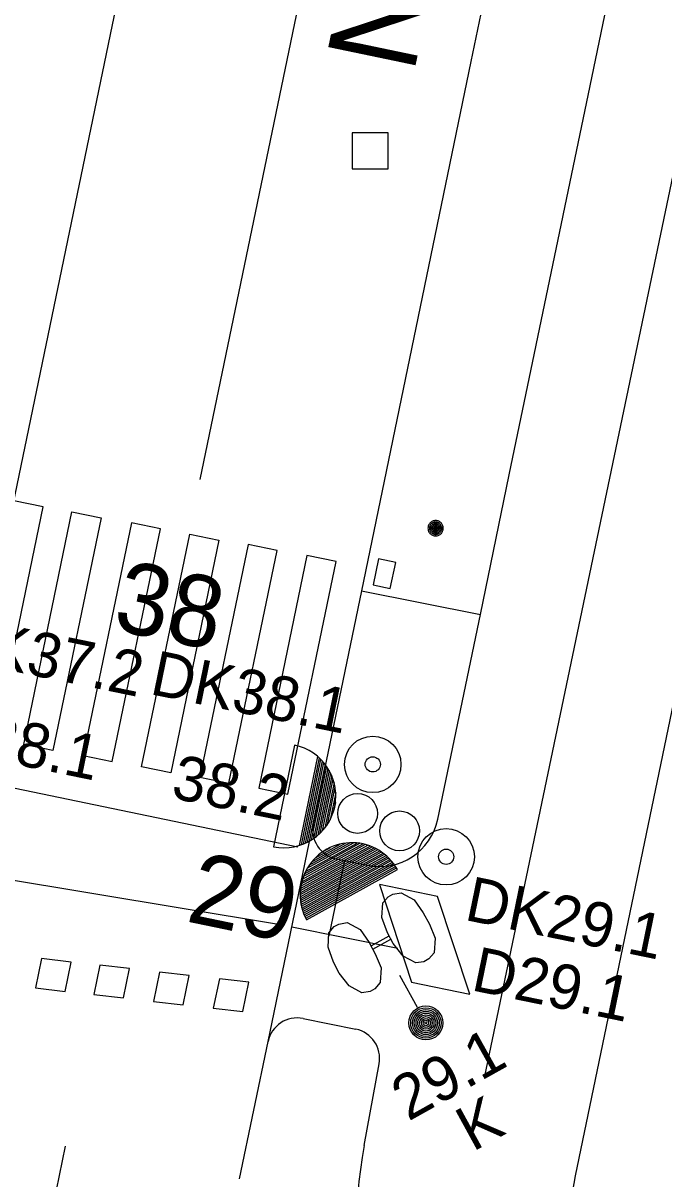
# Model space of a CAD drawing. Extents: x 81065 to 81486, y 452384 to 452681.
# Drawn here: x 81233.14 to 81243.92, y 452540.73 to 452560.19 of the extents above; entities that cross this region are included whole.
import ezdxf

# ---------------------------------------------------------------- set-up
doc = ezdxf.new("R2010")
doc.units = 0
for name, color, linetype in [('B-BH-AL-TOPOGRAFIE_STRAATNAAM-S', 7, 'Continuous'), ('B-BH-GR-BOOM-S', 7, 'Continuous'), ('B-BH-RI-GWA_RIOOLPUT-S', 7, 'Continuous'), ('B-BH-VH-KANTOPSLUITING-GV', 7, 'Continuous'), ('B-SRI-KOLK_COMBINATIE-S', 7, 'Continuous'), ('B-WE-VW-MARKERING_DWARS_OVERSTEEK_BLOKSTREEP50-G', 7, 'Continuous'), ('B-WE-VW-MARKERING_DWARS_OVERSTEEK_KANALISATIESTREEP50_010-G', 7, 'Continuous'), ('B-WE-VW-MARKERING_DWARS_OVERSTEEK_VOETGANGERS-G', 7, 'Continuous'), ('B-WE-VW-MARKERING_DWARS_STOPSTREEP_020-G', 7, 'Continuous'), ('B-WE-VW-MARKERING_LANGS_STREEP_13_010-G', 7, 'Continuous'), ('B-WE-VW-MARKERING_LANGS_STREEP_30270_010-G', 7, 'Continuous'), ('B-WE-VW-MARKERING_LANGS_STREEP_DOORGETROKKEN_010-G', 7, 'Continuous'), ('N-OI-KL-VRI_LUS_DETECTIE-G', 7, 'Continuous'), ('N-OI-KL-VRI_LUS_DETECTIE-T18', 7, 'Continuous'), ('N-WE-VW-VRI_ARMATUUR-S', 7, 'Continuous'), ('N-WE-VW-VRI_ARMATUUR-T18', 7, 'Continuous'), ('N-WE-VW-VRI_MAST-S', 7, 'Continuous'), ('N-WE-VW-VRI_RICHTINGNUMMER-T25', 7, 'Continuous')]:
    doc.layers.add(name, color=color, linetype=linetype)

msp = doc.modelspace()

# ---------------------------------------------------------------- linework, layer by layer
at = {"layer": 'B-BH-GR-BOOM-S'}
for points in [[(81239.949, 452551.685), (81239.95, 452551.671), (81239.952, 452551.658), (81239.955, 452551.645), (81239.96, 452551.633), (81239.966, 452551.621), (81239.974, 452551.609), (81239.982, 452551.599), (81239.992, 452551.589), (81240.002, 452551.581), (81240.014, 452551.573), (81240.026, 452551.567), (81240.038, 452551.562), (81240.051, 452551.559), (81240.064, 452551.557), (81240.078, 452551.556), (81240.091, 452551.557), (81240.105, 452551.559), (81240.118, 452551.562), (81240.13, 452551.567), (81240.142, 452551.573), (81240.154, 452551.581), (81240.164, 452551.589), (81240.174, 452551.599), (81240.182, 452551.609), (81240.19, 452551.621), (81240.196, 452551.633), (81240.2, 452551.645), (81240.204, 452551.658), (81240.206, 452551.671), (81240.207, 452551.685), (81240.206, 452551.698), (81240.204, 452551.712), (81240.2, 452551.725), (81240.196, 452551.737), (81240.19, 452551.749), (81240.182, 452551.761), (81240.174, 452551.771), (81240.164, 452551.781), (81240.154, 452551.789), (81240.142, 452551.797), (81240.13, 452551.803), (81240.118, 452551.807), (81240.105, 452551.811), (81240.091, 452551.813), (81240.078, 452551.814), (81240.064, 452551.813), (81240.051, 452551.811), (81240.038, 452551.807), (81240.026, 452551.803), (81240.014, 452551.797), (81240.002, 452551.789), (81239.992, 452551.781), (81239.982, 452551.771), (81239.974, 452551.761), (81239.966, 452551.749), (81239.96, 452551.737), (81239.955, 452551.725), (81239.952, 452551.712), (81239.95, 452551.698), (81239.949, 452551.685)], [(81239.974, 452551.685), (81239.974, 452551.674), (81239.976, 452551.663), (81239.979, 452551.653), (81239.983, 452551.642), (81239.987, 452551.633), (81239.993, 452551.624), (81240, 452551.615), (81240.008, 452551.607), (81240.017, 452551.6), (81240.026, 452551.594), (81240.035, 452551.59), (81240.046, 452551.586), (81240.056, 452551.583), (81240.067, 452551.581), (81240.078, 452551.581), (81240.089, 452551.581), (81240.1, 452551.583), (81240.11, 452551.586), (81240.12, 452551.59), (81240.13, 452551.594), (81240.139, 452551.6), (81240.148, 452551.607), (81240.156, 452551.615), (81240.162, 452551.624), (81240.168, 452551.633), (81240.173, 452551.642), (81240.177, 452551.653), (81240.18, 452551.663), (81240.182, 452551.674), (81240.182, 452551.685), (81240.182, 452551.696), (81240.18, 452551.707), (81240.177, 452551.717), (81240.173, 452551.727), (81240.168, 452551.737), (81240.162, 452551.746), (81240.156, 452551.755), (81240.148, 452551.763), (81240.139, 452551.769), (81240.13, 452551.775), (81240.12, 452551.78), (81240.11, 452551.784), (81240.1, 452551.787), (81240.089, 452551.789), (81240.078, 452551.789), (81240.067, 452551.789), (81240.056, 452551.787), (81240.046, 452551.784), (81240.035, 452551.78), (81240.026, 452551.775), (81240.017, 452551.769), (81240.008, 452551.763), (81240, 452551.755), (81239.993, 452551.746), (81239.987, 452551.737), (81239.983, 452551.727), (81239.979, 452551.717), (81239.976, 452551.707), (81239.974, 452551.696), (81239.974, 452551.685)], [(81239.996, 452551.685), (81239.997, 452551.676), (81239.998, 452551.668), (81240, 452551.66), (81240.003, 452551.652), (81240.007, 452551.644), (81240.012, 452551.637), (81240.017, 452551.63), (81240.023, 452551.624), (81240.03, 452551.619), (81240.037, 452551.614), (81240.045, 452551.61), (81240.053, 452551.607), (81240.061, 452551.605), (81240.069, 452551.604), (81240.078, 452551.603), (81240.086, 452551.604), (81240.095, 452551.605), (81240.103, 452551.607), (81240.111, 452551.61), (81240.119, 452551.614), (81240.126, 452551.619), (81240.133, 452551.624), (81240.139, 452551.63), (81240.144, 452551.637), (81240.149, 452551.644), (81240.152, 452551.652), (81240.156, 452551.66), (81240.158, 452551.668), (81240.159, 452551.676), (81240.16, 452551.685), (81240.159, 452551.693), (81240.158, 452551.702), (81240.156, 452551.71), (81240.152, 452551.718), (81240.149, 452551.726), (81240.144, 452551.733), (81240.139, 452551.74), (81240.133, 452551.746), (81240.126, 452551.751), (81240.119, 452551.756), (81240.111, 452551.759), (81240.103, 452551.763), (81240.095, 452551.765), (81240.086, 452551.766), (81240.078, 452551.767), (81240.069, 452551.766), (81240.061, 452551.765), (81240.053, 452551.763), (81240.045, 452551.759), (81240.037, 452551.756), (81240.03, 452551.751), (81240.023, 452551.746), (81240.017, 452551.74), (81240.012, 452551.733), (81240.007, 452551.726), (81240.003, 452551.718), (81240, 452551.71), (81239.998, 452551.702), (81239.997, 452551.693), (81239.996, 452551.685)], [(81240.019, 452551.685), (81240.02, 452551.679), (81240.021, 452551.673), (81240.022, 452551.667), (81240.024, 452551.661), (81240.027, 452551.656), (81240.031, 452551.65), (81240.034, 452551.646), (81240.039, 452551.641), (81240.043, 452551.638), (81240.049, 452551.634), (81240.054, 452551.631), (81240.06, 452551.629), (81240.066, 452551.628), (81240.072, 452551.627), (81240.078, 452551.626), (81240.084, 452551.627), (81240.09, 452551.628), (81240.096, 452551.629), (81240.102, 452551.631), (81240.107, 452551.634), (81240.112, 452551.638), (81240.117, 452551.641), (81240.122, 452551.646), (81240.125, 452551.65), (81240.129, 452551.656), (81240.132, 452551.661), (81240.134, 452551.667), (81240.135, 452551.673), (81240.136, 452551.679), (81240.137, 452551.685), (81240.136, 452551.691), (81240.135, 452551.697), (81240.134, 452551.703), (81240.132, 452551.709), (81240.129, 452551.714), (81240.125, 452551.719), (81240.122, 452551.724), (81240.117, 452551.729), (81240.112, 452551.732), (81240.107, 452551.736), (81240.102, 452551.739), (81240.096, 452551.741), (81240.09, 452551.742), (81240.084, 452551.743), (81240.078, 452551.744), (81240.072, 452551.743), (81240.066, 452551.742), (81240.06, 452551.741), (81240.054, 452551.739), (81240.049, 452551.736), (81240.043, 452551.732), (81240.039, 452551.729), (81240.034, 452551.724), (81240.031, 452551.719), (81240.027, 452551.714), (81240.024, 452551.709), (81240.022, 452551.703), (81240.021, 452551.697), (81240.02, 452551.691), (81240.019, 452551.685)], [(81240.042, 452551.685), (81240.042, 452551.681), (81240.043, 452551.678), (81240.044, 452551.674), (81240.045, 452551.67), (81240.047, 452551.667), (81240.049, 452551.664), (81240.051, 452551.661), (81240.054, 452551.658), (81240.057, 452551.656), (81240.06, 452551.654), (81240.063, 452551.652), (81240.067, 452551.651), (81240.071, 452551.65), (81240.074, 452551.649), (81240.078, 452551.649), (81240.082, 452551.649), (81240.085, 452551.65), (81240.089, 452551.651), (81240.093, 452551.652), (81240.096, 452551.654), (81240.099, 452551.656), (81240.102, 452551.658), (81240.104, 452551.661), (81240.107, 452551.664), (81240.109, 452551.667), (81240.111, 452551.67), (81240.112, 452551.674), (81240.113, 452551.678), (81240.114, 452551.681), (81240.114, 452551.685), (81240.114, 452551.689), (81240.113, 452551.692), (81240.112, 452551.696), (81240.111, 452551.7), (81240.109, 452551.703), (81240.107, 452551.706), (81240.104, 452551.709), (81240.102, 452551.711), (81240.099, 452551.714), (81240.096, 452551.716), (81240.093, 452551.718), (81240.089, 452551.719), (81240.085, 452551.72), (81240.082, 452551.721), (81240.078, 452551.721), (81240.074, 452551.721), (81240.071, 452551.72), (81240.067, 452551.719), (81240.063, 452551.718), (81240.06, 452551.716), (81240.057, 452551.714), (81240.054, 452551.711), (81240.051, 452551.709), (81240.049, 452551.706), (81240.047, 452551.703), (81240.045, 452551.7), (81240.044, 452551.696), (81240.043, 452551.692), (81240.042, 452551.689), (81240.042, 452551.685)], [(81240.065, 452551.685), (81240.065, 452551.684), (81240.065, 452551.682), (81240.066, 452551.681), (81240.066, 452551.68), (81240.067, 452551.679), (81240.068, 452551.677), (81240.068, 452551.676), (81240.069, 452551.675), (81240.07, 452551.675), (81240.072, 452551.674), (81240.073, 452551.673), (81240.074, 452551.673), (81240.075, 452551.672), (81240.077, 452551.672), (81240.078, 452551.672), (81240.079, 452551.672), (81240.081, 452551.672), (81240.082, 452551.673), (81240.083, 452551.673), (81240.084, 452551.674), (81240.086, 452551.675), (81240.087, 452551.675), (81240.088, 452551.676), (81240.088, 452551.677), (81240.089, 452551.679), (81240.09, 452551.68), (81240.09, 452551.681), (81240.091, 452551.682), (81240.091, 452551.684), (81240.091, 452551.685), (81240.091, 452551.686), (81240.091, 452551.688), (81240.09, 452551.689), (81240.09, 452551.69), (81240.089, 452551.691), (81240.088, 452551.693), (81240.088, 452551.694), (81240.087, 452551.695), (81240.086, 452551.695), (81240.084, 452551.696), (81240.083, 452551.697), (81240.082, 452551.697), (81240.081, 452551.698), (81240.079, 452551.698), (81240.078, 452551.698), (81240.077, 452551.698), (81240.075, 452551.698), (81240.074, 452551.697), (81240.073, 452551.697), (81240.072, 452551.696), (81240.07, 452551.695), (81240.069, 452551.695), (81240.068, 452551.694), (81240.068, 452551.693), (81240.067, 452551.691), (81240.066, 452551.69), (81240.066, 452551.689), (81240.065, 452551.688), (81240.065, 452551.686), (81240.065, 452551.685)]]:
    msp.add_lwpolyline(points, dxfattribs=at)
at = {"layer": 'B-BH-RI-GWA_RIOOLPUT-S'}
for p, q in [((81239.282, 452558.342), (81238.675, 452558.342)), ((81238.675, 452558.342), (81238.675, 452557.735)), ((81239.282, 452557.735), (81239.282, 452558.342)), ((81238.675, 452557.735), (81239.282, 452557.735))]:
    msp.add_line(p, q, dxfattribs=at)
at = {"layer": 'B-BH-VH-KANTOPSLUITING-GV'}
for p, q in [((81246.695, 452618.418), (81232.053, 452547.692)), ((81250, 452577.378), (81242.428, 452540.786)), ((81241.155, 452561.875), (81240.671, 452559.538)), ((81242.676, 452559.132), (81243.158, 452561.455)), ((81240.671, 452559.538), (81239.318, 452552.994)), ((81241.317, 452552.583), (81242.676, 452559.132)), ((81239.318, 452552.994), (81238.829, 452550.629)), ((81240.83, 452550.234), (81241.317, 452552.583)), ((81238.829, 452550.629), (81240.83, 452550.234)), ((81237.258, 452543.046), (81238.018, 452546.712)), ((81238.407, 452546.121), (81238.932, 452546.012)), ((81237.847, 452543.434), (81238.736, 452543.253)), ((81236.779, 452540.734), (81237.258, 452543.046)), ((81238.875, 452541.294), (81239.128, 452542.673))]:
    msp.add_line(p, q, dxfattribs=at)
for points in [[(81238.829, 452550.629), (81238.018, 452546.712)], [(81240.115, 452546.788), (81240.83, 452550.234)]]:
    msp.add_lwpolyline(points, dxfattribs=at)
for centre, radius, start, end in [((81238.508, 452546.61), 0.5, 168.2954, 258.2954), ((81239.134, 452546.991), 1, 258.2954, 348.2731), ((81237.748, 452542.944), 0.5, 78.4729, 168.2954), ((81238.636, 452542.763), 0.5, 349.6049, 78.4729), ((81246.744, 452539.851), 8, 169.6049, 262.3134), ((81247.324, 452539.772), 5, 168.3092, 262.3134)]:
    msp.add_arc(centre, radius, start, end, dxfattribs=at)
at = {"layer": 'B-SRI-KOLK_COMBINATIE-S'}
for p, q in [((81239.117, 452551.17), (81239.026, 452550.732)), ((81239.406, 452551.11), (81239.117, 452551.17)), ((81239.315, 452550.672), (81239.406, 452551.11)), ((81239.026, 452550.732), (81239.315, 452550.672))]:
    msp.add_line(p, q, dxfattribs=at)
at = {"layer": 'B-WE-VW-MARKERING_DWARS_OVERSTEEK_BLOKSTREEP50-G'}
msp.add_line((81232.02, 452547.512), (81237.759, 452546.324), dxfattribs=at)
for points in [[(81233.449, 452544.442), (81233.347, 452543.948), (81233.846, 452543.889), (81233.947, 452544.383)], [(81234.428, 452544.333), (81234.327, 452543.839), (81234.825, 452543.78), (81234.927, 452544.274)], [(81235.432, 452544.214), (81235.33, 452543.72), (81235.829, 452543.665), (81235.931, 452544.16)], [(81236.44, 452544.1), (81236.338, 452543.606), (81236.837, 452543.549), (81236.938, 452544.043)]]:
    msp.add_lwpolyline(points, close=True, dxfattribs=at)
at = {"layer": 'B-WE-VW-MARKERING_DWARS_OVERSTEEK_KANALISATIESTREEP50_010-G'}
msp.add_line((81231.802, 452545.953), (81237.4, 452545.029), dxfattribs=at)
at = {"layer": 'B-WE-VW-MARKERING_DWARS_OVERSTEEK_VOETGANGERS-G'}
for points in [[(81232.984, 452552.147), (81232.174, 452548.23), (81232.663, 452548.128), (81233.474, 452552.045)], [(81233.15, 452548.045), (81233.96, 452551.962), (81234.45, 452551.861), (81233.639, 452547.944)], [(81234.959, 452551.777), (81234.148, 452547.86), (81234.638, 452547.759), (81235.448, 452551.676)], [(81235.132, 452547.669), (81235.943, 452551.586), (81236.432, 452551.484), (81235.622, 452547.567)], [(81236.922, 452551.41), (81236.111, 452547.493), (81236.601, 452547.392), (81237.411, 452551.309)], [(81237.913, 452551.226), (81237.103, 452547.309), (81237.592, 452547.207), (81238.403, 452551.124)]]:
    msp.add_lwpolyline(points, close=True, dxfattribs=at)
at = {"layer": 'B-WE-VW-MARKERING_DWARS_STOPSTREEP_020-G'}
msp.add_line((81238.289, 452544.82), (81238.553, 452546.091), dxfattribs=at)
at = {"layer": 'B-WE-VW-MARKERING_LANGS_STREEP_13_010-G'}
for p, q in [((81249.633, 452617.81), (81236.113, 452552.506)), ((81233.846, 452541.285), (81227.841, 452511.692))]:
    msp.add_line(p, q, dxfattribs=at)
at = {"layer": 'B-WE-VW-MARKERING_LANGS_STREEP_30270_010-G'}
msp.add_line((81256.39, 452616.632), (81240.898, 452542.462), dxfattribs=at)
at = {"layer": 'B-WE-VW-MARKERING_LANGS_STREEP_DOORGETROKKEN_010-G'}
msp.add_line((81237.658, 452544.977), (81239.441, 452544.62), dxfattribs=at)
at = {"layer": 'N-OI-KL-VRI_LUS_DETECTIE-G'}
for p, q in [((81239.131, 452545.69), (81239.672, 452544.046)), ((81240.11, 452545.489), (81239.131, 452545.69)), ((81240.651, 452543.844), (81240.11, 452545.489)), ((81239.672, 452544.046), (81240.651, 452543.844))]:
    msp.add_line(p, q, dxfattribs=at)
at = {"layer": 'N-WE-VW-VRI_ARMATUUR-S'}
for p, q in [((81237.702, 452548.036), (81237.35, 452546.322)), ((81238.091, 452547.844), (81237.783, 452546.346)), ((81238.117, 452547.822), (81237.815, 452546.355)), ((81238.143, 452547.798), (81237.848, 452546.367)), ((81238.169, 452547.77), (81237.882, 452546.381)), ((81238.194, 452547.744), (81237.916, 452546.399)), ((81238.218, 452547.712), (81237.951, 452546.416)), ((81238.241, 452547.68), (81237.986, 452546.437)), ((81238.264, 452547.644), (81238.024, 452546.459)), ((81238.288, 452547.606), (81238.058, 452546.486)), ((81238.312, 452547.564), (81238.095, 452546.517)), ((81238.33, 452547.517), (81238.131, 452546.551)), ((81238.351, 452547.466), (81238.171, 452546.59)), ((81238.369, 452547.405), (81238.214, 452546.638)), ((81238.385, 452547.335), (81238.255, 452546.699)), ((81238.397, 452547.24), (81238.302, 452546.779)), ((81238.392, 452547.067), (81238.367, 452546.939)), ((81237.799, 452545.55), (81239.11, 452546.276)), ((81237.802, 452545.586), (81239.077, 452546.292)), ((81237.803, 452545.623), (81239.045, 452546.308)), ((81237.809, 452545.661), (81239.012, 452546.324)), ((81237.815, 452545.698), (81238.974, 452546.336)), ((81237.826, 452545.736), (81238.936, 452546.351)), ((81237.839, 452545.78), (81238.897, 452546.365)), ((81237.851, 452545.821), (81238.851, 452546.373)), ((81237.87, 452545.866), (81238.805, 452546.382)), ((81237.891, 452545.909), (81238.757, 452546.387)), ((81237.918, 452545.962), (81238.698, 452546.391)), ((81237.95, 452546.013), (81238.636, 452546.392)), ((81237.994, 452546.071), (81238.563, 452546.386)), ((81238.058, 452546.14), (81238.472, 452546.37)), ((81238.195, 452546.251), (81238.308, 452546.314)), ((81237.796, 452545.517), (81239.139, 452546.255)), ((81237.8, 452545.448), (81239.195, 452546.217)), ((81237.801, 452545.482), (81239.165, 452546.238)), ((81237.803, 452545.418), (81239.22, 452546.197)), ((81237.807, 452545.385), (81239.243, 452546.179)), ((81237.813, 452545.354), (81239.268, 452546.157)), ((81237.82, 452545.324), (81239.29, 452546.135)), ((81237.828, 452545.292), (81239.31, 452546.112)), ((81237.835, 452545.264), (81239.332, 452546.091)), ((81237.845, 452545.236), (81239.352, 452546.067)), ((81237.855, 452545.206), (81239.369, 452546.042)), ((81237.869, 452545.178), (81239.387, 452546.018)), ((81237.879, 452545.149), (81239.404, 452545.994)), ((81237.893, 452545.122), (81239.421, 452545.967)), ((81237.908, 452545.096), (81239.436, 452545.942)), ((81239.279, 452545.481), (81239.358, 452545.525)), ((81239.358, 452545.525), (81239.498, 452545.549)), ((81239.498, 452545.549), (81239.715, 452545.428)), ((81239.174, 452545.132), (81239.19, 452545.379)), ((81239.19, 452545.379), (81239.279, 452545.481)), ((81239.715, 452545.428), (81239.866, 452545.213)), ((81239.266, 452544.876), (81239.174, 452545.132)), ((81239.866, 452545.213), (81239.972, 452545.021)), ((81238.281, 452544.874), (81238.371, 452544.984)), ((81238.371, 452544.984), (81238.452, 452545.023)), ((81238.452, 452545.023), (81238.592, 452545.048)), ((81238.592, 452545.048), (81238.808, 452544.93)), ((81238.808, 452544.93), (81238.961, 452544.713)), ((81239.972, 452545.021), (81240.068, 452544.783)), ((81238.269, 452544.633), (81238.281, 452544.874)), ((81238.961, 452544.713), (81239.061, 452544.522)), ((81238.993, 452544.659), (81239.295, 452544.825)), ((81239.021, 452544.602), (81239.324, 452544.766)), ((81239.364, 452544.697), (81239.266, 452544.876)), ((81240.068, 452544.783), (81240.056, 452544.536)), ((81238.359, 452544.379), (81238.269, 452544.633)), ((81239.061, 452544.522), (81239.16, 452544.285)), ((81239.529, 452544.485), (81239.364, 452544.697)), ((81240.056, 452544.536), (81239.965, 452544.436)), ((81238.457, 452544.199), (81238.359, 452544.379)), ((81239.743, 452544.368), (81239.529, 452544.485)), ((81239.881, 452544.39), (81239.743, 452544.368)), ((81239.965, 452544.436), (81239.881, 452544.39)), ((81238.623, 452543.985), (81238.457, 452544.199)), ((81239.16, 452544.285), (81239.147, 452544.038)), ((81239.773, 452543.621), (81239.476, 452544.155)), ((81238.837, 452543.867), (81238.623, 452543.985)), ((81239.057, 452543.931), (81238.976, 452543.889)), ((81239.147, 452544.038), (81239.057, 452543.931)), ((81238.976, 452543.889), (81238.837, 452543.867))]:
    msp.add_line(p, q, dxfattribs=at)
for centre, radius in [((81239.02, 452547.711), 0.475), ((81239.02, 452547.711), 0.128), ((81240.255, 452546.156), 0.475), ((81240.255, 452546.156), 0.128), ((81239.914, 452543.359), 0.286), ((81239.914, 452543.359), 0.256), ((81239.914, 452543.359), 0.226), ((81239.914, 452543.359), 0.196), ((81239.914, 452543.359), 0.166), ((81239.914, 452543.359), 0.136), ((81239.914, 452543.359), 0.106), ((81239.914, 452543.359), 0.0765), ((81239.914, 452543.359), 0.0465), ((81239.914, 452543.359), 0.0165)]:
    msp.add_circle(centre, radius, dxfattribs=at)
for centre, start, end in [((81237.526, 452547.179), 258.375, 78.375), ((81238.671, 452545.519), 28.889, 208.889)]:
    msp.add_arc(centre, 0.873, start, end, dxfattribs=at)
at = {"layer": 'N-WE-VW-VRI_MAST-S'}
for centre in [(81238.766, 452546.884), (81239.472, 452546.591)]:
    msp.add_circle(centre, 0.335, dxfattribs=at)

# ---------------------------------------------------------------- texts
at = {"layer": 'B-BH-AL-TOPOGRAFIE_STRAATNAAM-S'}
msp.add_text('NEHERKADE', height=1.5, rotation=78.2165, dxfattribs=at).set_placement((81239.707, 452559.316))
at = {"layer": 'N-OI-KL-VRI_LUS_DETECTIE-T18'}
msp.add_text('D29.1', height=0.75, rotation=348.3917, dxfattribs=at).set_placement((81240.656, 452543.913))
at = {"layer": 'N-WE-VW-VRI_ARMATUUR-S'}
msp.add_text('K', height=0.75, rotation=28.6805, dxfattribs=at).set_placement((81240.701, 452541.184))
at = {"layer": 'N-WE-VW-VRI_ARMATUUR-T18'}
for s, rotation, p in [('DK37.2', 348.3917, (81231.796, 452549.518)), ('DK38.1', 348.3917, (81235.25, 452548.898)), ('38.1', 348.3917, (81232.424, 452547.83)), ('38.2', 348.3917, (81235.606, 452547.15)), ('DK29.1', 348.3917, (81240.544, 452545.097)), ('29.1', 29.2215, (81239.618, 452541.696))]:
    msp.add_text(s, height=0.75, rotation=rotation, dxfattribs=at).set_placement(p)
at = {"layer": 'N-WE-VW-VRI_RICHTINGNUMMER-T25'}
for s, rotation, p in [('38', 348.3917, (81234.619, 452549.984)), ('29', 348.2954, (81235.856, 452545.073))]:
    msp.add_text(s, height=1.2, rotation=rotation, dxfattribs=at).set_placement(p)

doc.saveas('drawing.dxf')
